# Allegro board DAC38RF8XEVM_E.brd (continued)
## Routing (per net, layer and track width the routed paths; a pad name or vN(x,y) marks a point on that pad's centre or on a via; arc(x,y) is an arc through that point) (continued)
VDD: length 143.1
  TOP w0.127: v1(68.5,30.2) 69.14,30.84 69.14,35.74 64.41,40.46 64.41,48.54 64.14,48.82 59.56,48.82 58.93,49.45 58.93,51.77 59.51,52.35 v1(59.51,52.4)
  TOP w0.305: v1(33.19,25.81) v1(33.99,26.61) ; v1(33.19,25.81) 33.15,25.81 ; v1(33.19,25.81) v1(33.19,25.01) ; v1(33.19,25.81) v1(33.99,25.81) ; v1(33.19,25.81) 33.55,25.45 33.63,25.45 ; v1(33.19,25.81) v1(33.19,26.61) ; v1(33.99,26.61) 34.37,26.23 ; v1(33.99,26.61) v1(33.19,27.41) ; v1(33.99,26.61) v1(33.99,25.81) ; v1(33.99,26.61) v1(32.39,25.81) ; v1(33.99,26.61) v1(33.19,26.61) ; v1(33.99,26.61) v1(33.19,25.01) ; v1(33.99,26.61) v1(33.99,27.41) ; v1(33.19,22.61) v1(33.19,23.41) v1(33.19,24.21) v1(33.19,25.01) ; 34.37,26.23 v1(33.99,25.81) ; 34.37,26.23 v1(34.79,25.81) ; v1(33.99,25.81) v1(33.19,27.41) ; v1(33.99,25.81) 33.63,25.45 ; v1(33.99,25.81) v1(34.79,25.81) ; v1(33.99,25.81) v1(33.19,26.61) ; v1(33.19,27.41) 33.63,27.41 ; v1(33.19,27.41) v1(33.19,26.61) ; v1(33.99,27.41) v1(33.19,26.61) ; v1(33.99,27.41) v1(33.19,25.01) ; v1(33.99,27.41) 33.63,27.41 ; v1(33.19,26.61) 32.77,25.43 ; v1(33.19,26.61) v1(32.39,25.81) ; v1(33.19,26.61) v1(34.79,25.81) ; 33.15,25.81 32.77,25.43 ; 33.15,25.81 v1(32.39,25.81) ; v1(33.19,25.01) 32.94,25.27 ; v1(33.19,25.01) 33.63,25.45 ; 33.63,27.41 32.94,25.27 ; 32.94,25.27 32.77,25.43 ; 32.77,25.43 v1(32.39,25.81) ; v1(32.39,25.81) v1(31.59,25.01)
  L3_PWR w0.102: 34.52,26.92 34.73,26.99 34.95,26.99 35.18,26.76 35.18,26.67 35.21,26.7 35.21,26.77 35.43,26.99 35.77,26.99 36.07,26.7 ; 31.45,24.64 31.45,24.61 31.21,24.37 31.21,24.05 31.4,23.86 ; 31.47,23.8 31.47,23.79 31.43,23.79 31.21,23.57 31.21,23.22 31.55,22.89
  L3_PWR w0.127: 58.75,26.77 58.43,27.09 57.96,27.09 57.64,26.77 57.48,26.77
  L4_SIG w0.305: 32.77,25.43 v1(32.39,25.81) ; 32.77,25.43 33.19,25.43 ; 32.77,25.43 32.77,25.81 ; v1(32.39,25.81) 32.79,26.21 ; v1(32.39,25.81) v1(31.59,25.01) ; v1(32.39,25.81) 32.77,25.81 ; v1(33.19,27.41) v1(33.99,27.41) ; v1(33.19,27.41) v1(33.99,26.61) ; v1(33.19,27.41) v1(33.19,26.61) ; v1(33.99,27.41) v1(33.19,26.61) ; v1(33.99,27.41) v1(33.99,26.61) ; v1(33.99,25.81) 34.26,25.81 ; v1(33.99,25.81) 33.6,25.43 ; v1(33.99,25.81) v1(33.19,26.61) ; v1(33.99,25.81) v1(33.99,26.61) ; v1(33.99,25.81) 33.6,25.81 ; 34.26,25.81 v1(34.79,25.81) 34.41,26.19 ; 34.26,25.81 34.26,26.03 34.41,26.19 ; 33.19,25.43 v1(33.19,25.81) ; 33.19,25.43 v1(33.19,25.01) ; v1(33.19,25.81) 32.77,25.81 ; v1(33.19,25.81) 33.19,26.21 ; v1(33.19,25.81) 33.6,25.81 ; v1(33.19,25.81) v1(33.99,26.61) ; v1(33.19,25.01) 33.6,25.43 ; v1(33.19,25.01) v1(33.19,24.21) v1(33.19,23.41) ; 33.6,25.43 33.6,25.81 ; v1(33.99,26.61) v1(33.19,26.61) ; v1(33.99,26.61) 34.41,26.19 ; 33.19,26.21 32.79,26.21 ; 33.19,26.21 v1(33.19,26.61) ; 32.79,26.21 v1(33.19,26.61)
  L6_PWR_SIG w0.305: v1(59.51,52.4) v1(59.51,53.52) 59.51,59.54 61.82,61.85 61.82,63.5 65.2,66.88 v1(65.94,66.88)
  BOTTOM w0.305: C117.1 33.18,25 v1(33.19,25.01) v1(33.99,25.81) ; C117.1 v1(33.19,24.21) v1(33.19,23.41) C118.1 ; C117.1 33.16,25.06 ; C117.1 33.63,27.41 ; v1(33.19,26.61) C127.1 34.8,25.81 v1(33.99,26.61) ; v1(33.19,26.61) v1(32.39,25.81) ; v1(33.19,26.61) v1(33.19,27.41) ; v1(33.19,26.61) v1(33.99,26.61) ; v1(33.19,26.61) v1(33.99,27.41) v1(33.99,26.61) ; v1(33.19,26.61) v1(33.99,25.81) ; v1(33.19,26.61) v1(33.19,25.81) ; v1(33.99,26.61) v1(32.39,25.81) ; v1(33.99,26.61) v1(33.19,25.81) ; v1(33.99,26.61) 32.69,25.53 ; v1(33.99,26.61) 33.99,26.23 ; v1(33.99,26.61) v1(33.19,27.41) ; C122.1 31.65,25.04 32.39,25.78 v1(32.39,25.81) ; 32.69,25.53 32.41,25.81 ; 32.69,25.53 32.96,25.26 ; 32.41,25.81 v1(33.19,25.81) ; 32.41,25.81 v1(32.39,25.81) ; 33.16,25.06 32.96,25.26 ; 33.16,25.06 33.16,25.4 ; 32.96,25.26 v1(33.19,27.41) ; v1(33.19,25.81) v1(33.99,25.81) ; v1(33.19,25.81) 33.16,25.79 33.16,25.4 ; v1(33.19,27.41) v1(33.99,25.81) ; v1(33.99,25.81) 33.99,26.23 ; v1(33.99,25.81) v1(34.79,25.81) ; 33.99,26.23 33.16,25.4
  BOTTOM w0.381: v1(33.99,27.41) v1(33.19,27.41)
  vias: v1(64.87,28.8) v1(65.63,28.8) v1(66.4,30.25) v1(66.4,28.81) v1(67.41,30.23) v1(67.46,28.8) v1(68.48,28.78) v2(33.28,21.31)
VDDE: length 20
  TOP w0.305: v1(31.59,26.61) v1(32.39,27.41) v1(31.59,28.21) 31.59,28.21 arc(31.99,28.59) 32.37,28.99 v1(32.39,29.01)
  L3_PWR w0.102: 32.81,28.37 32.79,28.37 32.66,28.5 ; 32.81,28.37 32.81,28.08 32.72,27.99 ; 32.81,28.37 32.81,28.39 33.05,28.63 ; 32.81,28.37 32.84,28.4 32.84,28.45 ; 32.74,28.68 32.84,28.45 ; 32.84,28.45 32.72,28.58 ; 32.84,28.45 32.84,28.6 ; 33.49,30.94 33.4,30.94 33.4,31.14 ; 33.49,30.94 33.49,30.85 33.57,30.85 ; 33.49,30.94 33.49,31.1 33.48,31.12 ; 33.6,31.27 33.57,31.23 33.57,30.85 ; 33.17,29.43 33.21,29.39 33.35,29.39 33.57,29.17 33.57,28.85 33.35,28.63 33.05,28.63 ; 33.17,29.43 33.35,29.43 33.57,29.66 33.57,29.97 33.35,30.19 33.21,30.19 33.17,30.23 ; 33.17,29.43 33.05,29.43 ; 32.57,27.84 32.72,27.99 ; 32.72,27.99 32.72,27.69 ; 33.17,30.23 33.35,30.23 33.57,30.45 33.57,30.85 ; 33.17,30.23 32.84,30.23 ; 32.84,28.6 32.92,28.6 ; 32.84,28.6 32.84,28.68 ; 33.05,28.63 33.03,28.63 32.96,28.7 ; 32,31.27 32,31.58 32.15,31.73
  L3_PWR w0.127: 32.56,31.83 32.54,31.81 32.23,31.81 32.15,31.73
  L4_SIG w0.305: v1(31.59,26.61) v1(32.39,27.41) v1(31.59,28.21) 31.59,28.21 arc(31.99,28.59) 32.37,28.99 v1(32.39,29.01)
  BOTTOM w0.254: 31.65,28.22 31.65,28.28 31.93,28.58 32.05,28.71 32.05,28.72 32.32,29.01 v1(32.39,29.01)
  BOTTOM w0.305: v1(32.39,27.41) 32.37,27.43 32.28,27.43 ; v1(34.52,35.13) 34.34,34.95 C119.1 33.68,34.95 v1(33.53,35.1) ; C125.1 32.38,29.01 v1(32.39,29.01) ; 32.28,27.43 C446.1 31.61,26.59 v1(31.59,26.61) ; 32.28,27.43 31.65,28.22 31.6,28.22 v1(31.59,28.21)
  vias: v1(48.03,37.03) v1(48.03,36.17) v1(49.25,37.06) v1(49.28,36.17)
VDDE_09:
  vias: v1(50.6,37.03) v1(50.6,36.25) v1(51.97,37.06) v1(51.97,36.22) v1(59.79,42.93) v1(59.82,42.06) v1(60.81,42.93) v1(60.83,42.06) v1(61.82,42.93) v1(61.85,42.06)
VDDOUT18:
  vias: v1(27.59,28.21) v1(27.59,27.41)
+1P8V:
  vias: v1(53.44,46.13) v1(53.44,45.19) v1(54.56,46.13) v1(54.56,45.19) v1(63.96,34.93) v1(63.96,33.81) v1(64.52,34.93) v1(64.52,33.81) v1(70.76,32.69) v1(70.76,32.13) v1(71.88,32.69) v1(71.88,32.13) v1(80.92,34.65) v1(80.92,34.09) v1(82.04,34.65) v1(82.04,34.09) v1(84.84,34.59) v1(84.84,34.04) v1(85.95,34.59) v1(85.95,34.04) v1(89,34.52) v1(89,33.96) v1(90.12,34.52) v1(90.12,33.96) v1(92.94,34.52) v1(92.94,33.96) v1(94.06,34.52) v1(94.06,33.96) v1(101.6,34.44) v1(101.6,33.88) v1(102.72,34.44) v1(102.72,33.88)
ALARM: length 57.1
  TOP w0.102: v1(30.79,29.81) 30.79,29.82 30.41,30.19 30.41,30.77 30.63,30.99 30.92,30.99 31.18,31.25 31.18,31.58 31.03,31.73
  TOP w0.127: 26.75,39.85 30.71,35.89 30.71,32.05 31.03,31.73
  TOP w0.152: v1(26.75,40.84) 26.75,39.85
  L3_PWR w0.127: TP9.1 33.55,60.2 29.36,56.01 29.08,56.01 28.46,55.38 28.46,55.01 27.93,54.48 21.84,54.48 20.15,52.79 20.15,45.38 20.79,44.74 20.8,44.74 21.07,44.47 21.07,44.47 23.04,42.49 26.16,42.49 26.75,41.91 v1(26.75,40.84)
AMUX0: length 64.4
  L4_SIG w0.102: v1(34.79,27.41) 35.17,27.03 35.86,27.03 36.56,26.33 36.56,23.3 36.79,23.08
  L4_SIG w0.127: v1(10.56,50.36) 8.5,50.36 7.59,49.45 7.59,45.57 8.76,44.4 11.68,44.4 13.77,42.32 13.77,41.43 14.41,40.78 15.55,40.78 16.32,40.01 16.32,39.64 16.14,39.47 16.14,39.03 17.27,37.9 18.11,37.9 20.91,35.09 21.01,35.09 21.27,34.83 21.27,31.66 22.53,30.4 22.53,24.87 22.96,24.44 22.96,23.65 24.64,21.97 24.64,20.68 25.14,20.18 25.44,20.18 25.47,20.15 25.84,20.15 25.87,20.18 26.25,20.18 27.37,21.3 30.9,21.3 33.06,19.14 34.76,19.14 36.97,21.35 36.97,22.9 36.79,23.08
AMUX1: length 54.3
  L4_SIG w0.102: v1(34.79,26.61) 35.21,26.19 35.75,26.19 36.12,25.82 36.12,22.45 35.9,22.23 35.88,22.23 35.86,22.21
  L4_SIG w0.127: v1(8.56,49.43) 7.98,48.84 7.98,45.87 8.94,44.91 11.85,44.91 15.41,41.36 15.41,41.34 15.67,41.08 15.68,41.08 16.62,40.14 16.62,39.91 22.73,33.8 22.73,31.67 23.52,30.89 23.52,29.72 23.43,29.63 23.43,26.56 23.77,26.21 23.77,24.9 24.03,24.64 24.03,23.39 25.09,22.33 25.5,22.33 26.1,21.73 26.1,21.55 26.3,21.35 26.58,21.35 26.84,21.6 31.38,21.6 32.72,20.26 33.48,20.26 35.4,22.19 35.84,22.19 35.86,22.21
ATEST: length 36.2
  L4_SIG w0.102: 27.28,22.99 28.55,22.99 28.86,22.68 29.8,22.68 30.41,23.29 30.41,23.83 v1(30.79,24.21)
  L4_SIG w0.127: 27.28,22.99 26.77,23.51 26.77,35.94 21.77,40.94 20.65,40.94 15.38,46.22 v1(12.57,46.22)
CAR_SYSREF_M: length 8.5
  BOTTOM w0.229: R23.1 120.98,40.06 R24.1 120.02,40.26 119.35,40.26 116.2,43.4 116.2,44.75 116.15,44.81 U2.4
CAR_SYSREF_P: length 8.5
  BOTTOM w0.229: U2.3 116.65,44.81 116.59,44.75 116.59,43.56 118.41,41.74 118.69,41.74 118.79,41.84 119.07,41.84 119.27,41.64 119.27,41.35 119.18,41.26 119.18,40.97 119.51,40.64 119.99,40.64 R25.1 120.98,40.87 R22.1
CAR_SYSREFM: length 28
  BOTTOM w0.165: J20.G10 146.05,47.88 145.8,48.13 141.96,48.13 141.88,48.04 141.86,48.04
  BOTTOM w0.229: R23.2 122.16,40.08 122.35,40.27 133.77,40.27 141.55,48.04 141.86,48.04
CAR_SYSREFP: length 28
  BOTTOM w0.165: 141.86,48.43 141.88,48.43 141.92,48.38 145.79,48.38 146.05,48.64 J20.G9
  BOTTOM w0.229: R22.2 122.16,40.84 122.35,40.65 133.62,40.65 141.39,48.43 141.86,48.43
CLK-IN: length 3.4
  BOTTOM w0.483: T3.6 100.96,58.24 R34.1 97.6,58.24 R32.2
CLK_LAO_0M: length 27.1
  BOTTOM w0.165: 141.86,51.92 141.9,51.92 141.93,51.95 145.76,51.95 146.05,51.66 J20.G7
  BOTTOM w0.229: R57.2 123.29,47.09 124.61,47.09 125.65,46.05 127.48,46.05 128.45,47.02 129.97,47.02 130.91,46.08 132.66,46.08 133.45,46.86 135.59,46.86 140.65,51.92 141.86,51.92
CLK_LAO_0P: length 27.1
  BOTTOM w0.165: 141.86,52.3 141.88,52.3 141.98,52.2 145.78,52.2 146.05,52.48 J20.G6
  BOTTOM w0.229: R55.2 123.22,47.47 124.77,47.47 125.81,46.43 127.32,46.43 128.29,47.4 130.13,47.4 131.07,46.46 132.51,46.46 133.29,47.24 135.43,47.24 140.49,52.3 141.86,52.3
CLKIN1_N: length 6.6
  BOTTOM w0.229: U2.35 111.14,55.72 111.08,55.78 111.08,58.42 C37.2 109.54,59.89 v1(108.71,59.89)
CLKIN1_P: length 6
  BOTTOM w0.229: U2.34 110.64,55.72 110.7,55.78 110.7,58.21 109.45,59.46 109.05,59.46 C35.2
  vias: v1(108.71,59.13)
CLKINN: length 4.2
  BOTTOM w0.483: T3.3 105.49,60.78 R35.2 106.38,59.89 C36.1
CLKINP: length 4.2
  BOTTOM w0.483: C35.1 107.24,59.13 R29.1 106.4,59.11 R35.1 105.53,58.24 T3.1
CLKLA_0M: length 4
  BOTTOM w0.229: R57.1 122.33,46.84 R58.1 121.15,46.84 120.91,47.07 119.41,47.07 119.35,47.01 U2.63
CLKLA_0P: length 4
  BOTTOM w0.229: R55.1 122.33,47.65 R56.1 121.15,47.65 120.95,47.45 119.41,47.45 119.35,47.51 U2.62
CLKN: length 98
  BOTTOM w0.229: v2(30.55,19.11) 29.95,19.11 29.72,18.89 29.72,18.56 30.07,18.21 30.97,18.21 arc(31.21,18.31) 31.31,18.55 arc(31.65,18.9) 31.99,18.55 arc(32.1,18.31) 32.34,18.21 34.01,18.21 38.75,22.96 103.66,22.96 104.5,23.8 104.5,24.09 104.44,24.15 104.44,24.43 104.64,24.63 104.93,24.63 104.99,24.57 105.27,24.57 105.64,24.94 105.64,38.51 106.54,39.41 106.54,40.96 R36.2
CLKP: length 98
  BOTTOM w0.229: R31.2 106.92,40.96 106.92,39.25 106.02,38.35 106.02,24.78 103.82,22.58 38.91,22.58 34.16,17.83 29.91,17.83 29.34,18.4 29.34,18.88 29.11,19.11 v2(28.52,19.11)
CP1: length 35.2
  L6_PWR_SIG w0.305: v1(107.37,54.03) 111.23,54.03 113.26,56.06 113.28,56.06 113.31,56.09 113.34,56.09 113.44,56.18 114.27,56.18 116.28,58.19 124.54,58.19 129.59,63.25 v1(136.8,63.25)
  BOTTOM w0.305: v1(107.37,54.03) 107.37,54.02 U2.32
  vias: v1(137.57,63.25)
CP2: length 2.2
  TOP w0.305: v1(116.65,55.53) 116.65,54.88 C34.1 C33.1
  BOTTOM w0.305: U2.46 v1(116.65,55.53)
DAC_RESET: length 149.6
  L4_SIG w0.102: v1(29.99,29.81) 29.61,30.19 29.61,31.73
  L4_SIG w0.127: 29.61,31.73 29.61,34.09 26.5,37.2 25.95,37.2 24.66,38.49 24.66,38.96 14.45,49.17 14.45,54.71 17.2,57.45 19.35,57.45 v1(20.42,58.52) 24.05,62.15 25.1,62.15 26.26,63.32 29.13,63.32 29.42,63.61 29.42,64.02 29.71,64.31 33.03,64.31 33.11,64.22 35.31,64.22 35.4,64.31 35.4,64.31 35.51,64.41 36.84,64.41 37,64.25 39.23,64.25 39.93,64.95 43.18,64.95 43.61,64.52 50.42,64.52 51.33,63.6 61.19,63.6 62.48,64.9 70.23,64.9 72.75,62.38 81.67,62.38 81.88,62.17 82.25,62.17 82.58,62.5 83.04,62.5 83.27,62.26 86.52,62.26 86.78,62.52 91.2,62.52 93.14,64.47 94.82,64.47 95.55,63.73 97.95,63.73 100.37,66.14 117.2,66.14 118.64,64.7 v1(118.64,64.62) 121.14,64.62 SW1.2
  BOTTOM w0.127: R11.2 v1(118.64,64.62)
DAC_SCLK: length 43.1
  L4_SIG w0.127: v1(52.81,55.3) 52.81,55.19 52.3,54.69 49.98,54.69 48.89,55.78 46.28,55.78 43.92,53.42 43.14,53.42 42.67,53.89 41.97,53.89 41.86,53.77 38.93,53.77 38.92,53.78 38.55,53.78 38.54,53.77 34.79,53.77 34.78,53.76 33.82,53.76 33.41,53.35 29.29,53.35 29.09,53.56 28.72,53.56 28.59,53.43 27.06,53.43 26.34,54.15 22.61,54.15 22.36,53.9 21.26,53.9 20.61,53.25 v1(20.61,48.43)
  BOTTOM w0.127: U29.6 53.26,57.41 53.42,57.25 53.42,55.75 52.96,55.3 v1(52.81,55.3)
DAC_SDENB: length 40.7
  L4_SIG w0.127: v2(52.68,55.91) 52.58,56.01 49.83,56.01 48.92,56.92 46.1,56.92 44.27,55.09 42.19,55.09 41.95,54.85 41.36,54.85 41.33,54.83 40.96,54.83 40.94,54.85 40.21,54.85 40.01,54.65 30.31,54.65 30.18,54.78 29.81,54.78 29.76,54.72 20.56,54.72 19.63,53.8 19.63,50.75 18.6,49.71 v1(18.6,48.43)
DAC_SDIO: length 52.5
  L4_SIG w0.127: v2(52.68,56.91) 53.19,57.42 53.19,61.8 52.35,62.64 48.58,62.64 48.11,63.11 45.22,63.11 44.55,62.43 41.53,62.43 41.33,62.64 40.64,62.64 40.5,62.5 39.26,62.5 39.18,62.57 31.02,62.57 30.38,63.21 29.68,63.21 29.31,62.84 28.54,62.84 27.62,61.93 27.62,61.82 27.27,61.47 24.18,61.47 20.65,57.94 20.65,56.37 19.95,55.66 19.67,55.66 19.23,55.22 19.23,51.06 v1(16.59,48.43)
DAC_SDO: length 40.1
  L4_SIG w0.127: v2(52.68,56.41) 53.31,55.77 53.31,55.04 52.48,54.2 49.56,54.2 48.98,54.78 46.42,54.78 44.58,52.93 40.31,52.93 39.71,52.34 27.29,52.34 26.06,53.57 23.37,53.57 22.59,52.79 v1(22.59,47.51)
DACCLK_IN: length 3.3
  TOP w0.483: J1.1 5.33,8.1 R215.2
DACCLK_N: length 3.1
  TOP w0.229: C334.2 29.74,19.91 29.74,22.37 U1.A9
DACCLK_P: length 3.1
  TOP w0.229: U1.A10 29.36,22.44 29.36,19.96 C333.2
DACCLK_SE: length 4.1
  TOP w0.483: C370.2 26.75,14.13 R2.1 C25.1 R1.2
DACCLKSE: length 4.4
  TOP w0.483: R1.1 26.75,18.59 27.08,18.92 R3.1 27.08,21.38 arc(27.13,21.81) 27.29,22.21 arc(27.43,22.42) U1.A12
DCLKOUT4P: length 1.5
  BOTTOM w0.229: v1(108.03,49.53) 108.51,50.02 U2.24
DIV_IN: length 96.6
  TOP w0.483: R214.2 9.53,12.21 v1(9.52,12.22)
  BOTTOM w0.406: v1(9.52,12.22) 10.23,12.93 arc(10.8,13.77) 11,14.77 11,38.1 arc(11.22,39.21) 11.85,40.15 11.85,40.15 arc(12.42,40.53) 13.09,40.67 22,40.67 arc(22.86,40.49) 23.6,40 24.5,39.1 arc(25.22,38.62) 26.06,38.46 71.27,38.46 arc(72.97,38.79) 74.41,39.76 R243.1
  BOTTOM w0.483: R243.1 75.94,41.27 C378.1
DM: length 5.6
  BOTTOM w0.229: J16.2 7.25,56.43 7.46,56.64 8.15,56.64 9.87,54.91 10.57,54.91 R65.1
DP: length 5.6
  BOTTOM w0.229: J16.3 7.32,57.23 7.53,57.02 8.31,57.02 10.03,55.3 10.54,55.3 R66.1
DP0_C2M_N_A: length 131.8
  TOP w0.229: v2(151.13,56.52) 150.69,56.96 150.36,56.96 148.93,55.53 148.93,55.51 148.82,55.39 148.82,45.64 146.77,43.59 141.07,43.59 135.53,38.05 133.12,38.05 117.32,22.25 59.41,22.25 46.3,35.36 45.26,35.36 45.14,35.23 C24.1
DP0_C2M_P_A: length 131.8
  TOP w0.229: C23.1 45.14,35.92 45.31,35.74 46.46,35.74 59.57,22.63 117.17,22.63 132.96,38.43 135.38,38.43 140.91,43.97 146.61,43.97 148.44,45.8 148.44,55.55 148.55,55.66 148.55,55.69 150.2,57.34 150.69,57.34 v2(151.13,57.79)
DP1_C2M_N_A: length 124.4
  TOP w0.229: v2(153.67,31.12) 154.12,31.57 154.59,31.57 155.04,32.02 155.04,33.51 154.31,34.24 145.26,34.24 131.67,20.65 58.78,20.65 46.2,33.22 45.31,33.22 C21.1
DP1_C2M_P_A: length 124.3
  TOP w0.229: C22.1 45.34,32.84 46.04,32.84 58.62,20.27 131.83,20.27 144.15,32.6 arc(144.32,32.67) 144.48,32.6 arc(144.65,32.53) 144.81,32.6 144.97,32.75 arc(145.04,32.92) 144.97,33.08 arc(144.9,33.25) 144.97,33.41 145.41,33.86 149.62,33.86 arc(149.83,33.77) 149.92,33.55 arc(150.01,33.34) 150.23,33.25 150.31,33.25 arc(150.52,33.34) 150.61,33.55 arc(150.7,33.77) 150.91,33.86 154.15,33.86 154.66,33.35 154.66,32.17 154.43,31.95 154.11,31.95 v2(153.67,32.38)
DP2_C2M_N_A: length 117.4
  TOP w0.229: v2(153.67,26.03) 153.31,26.39 142.39,26.39 141.16,25.16 141.16,24.98 140.49,24.31 140.31,24.31 133.93,17.93 58.19,17.93 46.02,30.1 45.26,30.1 C18.1
DP2_C2M_P_A: length 117.4
  TOP w0.229: C19.1 45.39,30.48 46.18,30.48 58.35,18.31 133.78,18.31 142.23,26.77 153.16,26.77 153.67,27.28 v2(153.67,27.3)
DP3_C2M_N_A: length 121.6
  TOP w0.229: v2(153.67,20.95) 153.67,21.11 153.92,21.36 154.41,21.36 154.99,21.94 154.99,23.27 154.36,23.9 142.39,23.9 134.47,15.98 57.94,15.98 46.1,27.81 45.39,27.81 C17.1
DP3_C2M_P_A: length 121.6
  TOP w0.229: v2(153.67,22.23) 153.67,22 153.92,21.74 154.25,21.74 154.61,22.1 154.61,23.11 154.2,23.52 151.03,23.52 150.7,23.19 150.22,23.19 149.89,23.52 148.44,23.52 148.09,23.17 147.77,23.17 147.42,23.52 145.85,23.52 145.54,23.22 145.08,23.22 144.78,23.52 142.55,23.52 141.23,22.2 arc(141.17,22.07) 141.23,21.93 arc(141.28,21.8) 141.23,21.67 141.01,21.45 arc(140.88,21.39) 140.74,21.45 arc(140.61,21.5) 140.48,21.45 134.63,15.6 57.78,15.6 45.94,27.43 45.26,27.43 C16.1
DP4_C2M_N_A: length 120.4
  TOP w0.229: v2(153.67,15.88) 154.11,16.32 154.6,16.32 155.05,16.77 155.05,17.7 154.48,18.26 153.23,18.26 152.62,17.65 143.76,17.65 137.43,11.33 57.07,11.33 45.87,22.53 45.34,22.53 C13.1
DP4_C2M_P_A: length 120.4
  TOP w0.229: v2(153.67,17.14) 154.11,16.7 154.44,16.7 154.67,16.93 154.67,17.54 154.32,17.88 153.39,17.88 152.78,17.27 152.42,17.27 arc(152.18,17.17) 152.08,16.93 152.08,16.88 arc(151.73,16.54) 151.39,16.88 151.39,16.93 arc(151.29,17.17) 151.05,17.27 143.92,17.27 141.45,14.81 141.45,14.15 141.2,13.89 140.54,13.89 137.59,10.95 56.92,10.95 45.71,22.15 45.31,22.15 C14.1
DP5_C2M_N_A: length 119.3
  TOP w0.229: C10.1 45.34,17.2 45.8,17.2 56.29,6.71 141.14,6.71 141.43,6.99 arc(141.53,7.24) 141.43,7.48 141.41,7.5 arc(141.41,7.99) 141.9,7.99 141.92,7.97 arc(142.16,7.86) 142.4,7.97 143.23,8.79 153.9,8.79 154.66,9.55 154.66,9.72 arc(154.58,9.93) 154.37,10.01 154.37,10.01 arc(154.18,10.21) 154.37,10.4 154.47,10.4 arc(154.6,10.45) 154.66,10.59 154.66,11.01 154.43,11.23 154.11,11.23 v2(153.67,10.79)
DP5_C2M_P_A: length 119.1
  TOP w0.229: v2(153.67,12.06) 154.12,11.61 154.59,11.61 155.04,11.16 155.04,9.39 154.06,8.41 143.38,8.41 141.3,6.32 56.13,6.32 45.64,16.81 45.31,16.81 C11.1
DP6_C2M_N_A: length 114.1
  TOP w0.229: C8.1 45.31,19.48 45.74,19.48 56.51,8.71 139.22,8.71 144.27,13.77 151.97,13.77 v2(152.4,13.33)
DP6_C2M_P_A: length 114.1
  TOP w0.229: v2(152.4,14.61) 151.94,14.15 144.11,14.15 139.06,9.09 56.67,9.09 45.9,19.86 45.34,19.86 C9.1
DP7_C2M_N_A: length 115.9
  TOP w0.229: v2(152.4,18.41) 151.92,18.9 150.46,18.9 148.99,20.37 143.21,20.37 136.07,13.23 57.35,13.23 45.79,24.79 45.29,24.79 C5.1
DP7_C2M_P_A: length 115.9
  TOP w0.229: C6.1 45.36,25.17 45.95,25.17 57.51,13.61 135.91,13.61 143.05,20.75 149.15,20.75 150.62,19.28 151.99,19.28 v2(152.4,19.69)
EEDATA: length 4.6
  TOP w0.127: R74.1 36.6,50.8 v1(36.56,50.84) 36.56,51.06 36.91,51.41 36.91,52.62 U5.3
  BOTTOM w0.127: U4.61 v1(36.56,50.84)
EXTIO: length 2.3
  BOTTOM w0.102: 27.28,23.79 28.54,23.79 28.96,24.21 v1(29.19,24.21)
  BOTTOM w0.127: 27.28,23.79 27.07,23.79 C28.1
FMC_DAC_SCLK: length 149.6
  L4_SIG w0.127: v1(25.88,43.71) 25.88,43.61 29.11,40.39 29.69,40.39 30.59,39.48 30.59,39.06 30.85,38.8 31.07,38.8 31.92,37.95 31.92,37.71 32.93,36.69 33.39,36.69 34.51,35.57 34.99,35.57 35.64,34.92 35.64,34.47 37.88,32.22 37.88,32 38.58,31.3 38.58,30.43 41.48,27.53 54.79,27.53 57.05,25.27 118.24,25.27 118.4,25.11 122.24,25.11 127.48,30.35 127.48,30.78 127.97,31.27 128.32,31.27 132.47,35.42 133.49,35.42 134.53,36.46 137.47,36.46 137.89,36.04 141.48,36.04 141.97,35.55 144.83,35.55 145.41,36.13 145.41,36.4 145.81,36.8 146.09,36.8 146.55,37.26 146.55,37.52 147.26,38.24 147.53,38.24 147.82,38.53 147.82,38.79 148.53,39.51 148.8,39.51 149.36,40.08 149.36,40.21 149.78,40.63 151.18,40.63 151.71,41.16 151.71,41.96 v3(151.13,42.55)
  BOTTOM w0.127: R289.2 22.1,44.73 22.91,44.73 23.93,43.71 v1(25.88,43.71)
FMC_DAC_SDENB: length 146.7
  L4_SIG w0.127: v3(149.86,41.27) 149.29,40.7 148,40.7 147.82,40.52 147.82,39.8 147.53,39.51 147.11,39.51 146.55,38.94 146.55,38.53 146.13,38.12 145.83,38.12 145.43,37.71 145.43,37.41 144.99,36.97 136.66,36.97 136.55,36.86 132.23,36.86 125.17,29.79 104.65,29.79 104.01,30.43 100.96,30.43 99.78,31.61 94.73,31.61 94.53,31.41 92.75,31.41 92.73,31.43 83.93,31.43 83.76,31.61 69.74,31.61 69.19,31.06 65.71,31.06 64.33,29.68 61.05,29.68 60.1,30.63 57.15,30.63 56.29,29.77 55.52,29.77 54.89,30.4 52.53,30.4 52.12,30 49.3,30 48.95,30.35 43,30.35 42.55,29.9 41,29.9 38.99,31.9 38.99,32.15 37.09,34.05 36.7,34.05 36.2,34.55 36.2,35.5 34.89,36.8 33.86,36.8 33.16,37.5 33.16,37.85 32.9,38.11 32.37,38.11 31.48,39 31.48,39.43 31.22,39.69 30.98,39.69 28.18,42.48 28.18,42.58 27.92,42.84 27.83,42.84 26.52,44.15 v1(26.52,44.2)
  BOTTOM w0.127: v1(26.52,44.2) 24.14,44.21 23.19,45.16 19.84,45.16 R290.2
FMC_DAC_SDIO: length 149.6
  L4_SIG w0.127: v3(151.13,41.27) 150.55,41.86 146.97,41.86 146.61,41.5 146.61,39.86 146.26,39.51 146.06,39.51 145.28,38.72 145.28,38.53 144.92,38.18 141.28,38.18 141,37.9 132.61,37.9 124.9,30.19 106.46,30.19 103.43,33.22 66.31,33.22 64.76,31.67 61.54,31.67 61.49,31.72 54.48,31.72 54.15,31.39 49.07,31.39 48.54,30.86 41.17,30.86 40.08,31.95 40.08,32.23 38.94,33.38 38.56,33.38 37.49,34.44 37.49,34.72 35,37.21 33.88,37.21 33.46,37.63 33.46,37.98 33.03,38.42 32.68,38.42 31.79,39.31 31.79,39.71 31.39,40.11 31.08,40.11 27.15,44.04 v1(27.15,44.7)
  BOTTOM w0.127: R291.2 18.08,46 22.99,46 24.27,44.71 27.14,44.71 v1(27.15,44.7)
FMC_DAC_SDO: length 152.3
  L4_SIG w0.127: v1(25.27,43.15) 25.83,43.15 29.01,39.98 29.56,39.98 30.09,39.45 30.09,39.15 30.29,38.95 30.29,38.93 30.73,38.49 30.75,38.49 31.15,38.09 31.35,38.09 31.61,37.83 31.61,37.43 32.65,36.38 33.14,36.38 33.97,35.55 33.97,34.89 34.62,34.24 35,34.24 38.25,30.99 38.25,30.15 39.41,28.99 39.41,28.99 39.61,28.79 39.61,28.79 41.35,27.05 54.24,27.05 56.68,24.61 122.45,24.61 127.08,29.24 128.4,29.24 128.8,29.64 128.8,30.96 132.77,34.93 133.76,34.93 134.31,35.47 138.01,35.47 139.06,34.43 143.79,34.43 144.04,34.68 145.01,34.68 145.8,35.47 146.12,35.47 146.88,36.23 146.88,36.38 147.14,36.64 147.28,36.64 148.09,37.45 148.09,37.67 148.38,37.96 148.6,37.96 150.06,39.42 151.27,39.42 151.9,40.05 151.9,40.21 152.19,40.5 152.36,40.5 153.11,41.25 153.11,42.57 152.53,43.15 150.47,43.15 v3(149.86,42.55)
  BOTTOM w0.127: R288.2 v1(25.27,43.15)
FMC_LMK_CS: length 102.2
  L4_SIG w0.127: v1(56.11,59.18) 57.96,59.18 63.02,54.13 64.87,54.13 65.94,55.19 71.04,55.19 72.58,53.66 78.09,53.66 78.2,53.77 78.67,53.77 78.78,53.66 79.15,53.66 79.52,54.03 81.81,54.03 82.3,54.51 89.41,54.51 89.69,54.23 90.55,54.23 90.83,54.51 92.74,54.51 94.83,56.6 101.26,56.6 103.19,54.67 105.88,54.67 108.41,52.15 109.93,52.15 110.31,51.77 117.37,51.77 119,50.14 120.27,50.14 120.62,50.5 133.2,50.5 134.67,49.02 134.67,48.23 138.02,44.88 138.48,44.88 139.24,44.12 139.24,43.31 141.77,40.78 142.17,40.78 142.74,40.21 142.74,39.84 143.28,39.29 144.22,39.29 v3(144.78,38.73)
FMC_LMK_SCK: length 102.3
  L4_SIG w0.127: v3(146.05,41.27) 145.36,41.96 145.36,42.75 144.93,43.18 144.22,43.18 142.74,44.67 142.74,45.29 142.45,45.58 141.77,45.58 135.92,51.43 135.92,52.91 135.51,53.31 128.96,53.31 127.9,54.37 127.48,54.37 127.22,54.63 127.22,55.05 124.99,57.28 111.28,57.28 110.77,56.77 109.4,56.77 108.89,57.28 106.93,57.28 105.36,58.85 94.59,58.85 93.7,57.96 81.65,57.96 79.6,60.02 70.43,60.02 70.15,60.3 67.72,60.3 66.73,61.29 63.17,61.29 62.71,60.83 59,60.83 57.23,62.61 v1(56.11,62.61)
FMC_LMK_SDIO: length 103.9
  L4_SIG w0.127: v1(56.11,61.47) 57.3,61.47 61.11,57.66 63.3,57.66 63.6,57.96 68.2,57.96 68.29,58.05 70.12,58.05 70.4,57.77 72.33,57.77 74.24,59.69 78.91,59.69 82.8,55.8 84.83,55.8 85.13,55.5 86.26,55.5 86.56,55.8 92.41,55.8 94.97,58.37 104.85,58.37 107.48,55.74 107.48,55.69 109.11,54.05 114.96,54.05 114.97,54.06 118.45,54.06 121.12,51.4 134.22,51.4 136.99,48.62 137.89,48.62 139.55,46.96 139.55,46.26 142.8,43.01 142.8,42.56 143.3,42.05 143.44,42.05 144.12,41.37 144.12,41.23 144.69,40.67 145.39,40.67 v3(146.05,40.01)
FMC_LMK_SDO: length 102.6
  L4_SIG w0.127: v1(56.11,60.33) 57.63,60.33 63.3,54.66 64.77,54.66 65.89,55.78 71.45,55.78 72.57,54.66 81.48,54.66 82.26,55.44 84.77,55.44 85.06,55.14 86.72,55.14 86.98,55.41 89.2,55.41 89.91,54.7 90.28,54.7 90.65,55.07 92.48,55.07 95.38,57.96 104.7,57.96 108.24,54.42 108.27,54.42 109.84,52.84 118.86,52.84 120.75,50.95 133.34,50.95 136.58,47.71 136.61,47.71 138.84,45.49 139.24,45.49 140.88,43.85 140.88,42.49 141.32,42.05 142.33,42.05 142.82,41.55 142.82,41.26 143.3,40.78 144.01,40.78 v3(144.78,40.01)
FPGA_CLK1_N: length 20.4
  BOTTOM w0.165: J20.K5 141.86,54.36
  BOTTOM w0.229: C43.2 124.09,50.47 124.28,50.66 137.18,50.66 140.95,54.43 141.78,54.43 141.86,54.36
FPGA_CLK1_P: length 20.4
  BOTTOM w0.165: J20.K4 141.86,54.86
  BOTTOM w0.229: C42.2 124.09,51.23 124.28,51.04 137.02,51.04 140.79,54.81 141.81,54.81 141.86,54.86
FPGA_CLK1N: length 5.7
  BOTTOM w0.229: U2.52 119.35,52.52 119.41,52.58 119.73,52.58 120.52,51.79 120.52,51.31 121.16,50.67 121.92,50.67 R46.1 122.91,50.44 C43.1
FPGA_CLK1P: length 5.7
  BOTTOM w0.229: C42.1 122.91,51.26 R45.1 121.95,51.05 121.32,51.05 120.9,51.47 120.9,51.95 119.89,52.96 119.41,52.96 119.35,53.02 U2.51
FPGA_CLK2_N: length 22.5
  BOTTOM w0.165: 141.86,56.96 141.9,56.96 141.96,57.02 143.23,57.02 143.51,56.74 J20.J3
  BOTTOM w0.229: C48.2 123.3,53.37 123.49,53.56 137.83,53.56 141.24,56.96 141.86,56.96
FPGA_CLK2_P: length 22.5
  BOTTOM w0.165: J20.J2 143.51,57.53 143.26,57.28 141.96,57.28 141.9,57.34 141.86,57.34
  BOTTOM w0.229: 141.86,57.34 141.08,57.34 137.68,53.94 123.49,53.94 123.3,54.13 C47.2
FPGA_CLK2N: length 3.8
  BOTTOM w0.229: C48.1 122.12,53.34 R50.1 121.12,53.58 119.41,53.58 119.35,53.52 U2.50
FPGA_CLK2P: length 3.8
  BOTTOM w0.229: U2.49 119.35,54.02 119.41,53.96 121.17,53.96 R51.1 122.12,54.15 C47.1
FTDI_TCK: length 57.1
  L3_PWR w0.127: v1(51.8,59.78) 51.27,59.25 50.11,59.25 49.77,58.91 49.77,57.77 49.12,57.11 38.34,57.11 37.39,56.16 35.24,56.16 34.72,55.64 34.43,55.64 31.64,52.84 31.64,52.6 30.93,51.89 v1(26.06,51.89)
  L4_SIG w0.102: v1(33.99,29.81) 34,29.81 34.41,30.22 34.41,31.73
  L4_SIG w0.127: 34.41,31.73 31.88,34.26 31.88,34.82 31.21,35.5 31.2,35.5 30.94,35.76 30.94,35.76 26.61,40.09 26.44,40.09 26,40.53 26,40.7 24.26,42.44 24.26,50.09 v1(26.06,51.89)
FTDI_TDI: length 69.5
  L3_PWR w0.127: v1(23.65,53.09) 25.35,51.38 31.19,51.38 33.57,53.76 35.88,53.76 38.09,55.97 50.12,55.97 50.12,55.98 50.49,55.98 50.5,55.97 51.9,55.97 52.26,56.33 52.26,58.49 v2(52.68,58.91)
  L4_SIG w0.102: 36.09,31.73 36.09,29.69 35.83,29.43 34.56,29.43 34.39,29.26 34.39,28.62 v1(33.99,28.21)
  L4_SIG w0.127: 36.09,31.73 36.09,31.9 32.13,35.87 32.13,36.38 31.32,37.2 30.98,37.2 30.72,37.46 30.72,37.79 29.68,38.82 29.46,38.82 29.2,39.08 29.2,39.19 28.82,39.57 28.82,39.58 28.38,40.02 28.36,40.02 26.63,41.75 26.63,41.92 26.1,42.44 25.17,42.44 24.66,42.95 24.66,49.63 26.59,51.56 26.59,52.25 25.76,53.09 v1(23.65,53.09)
FTDI_TDO: length 70.4
  L3_PWR w0.127: v2(52.68,58.41) 52.84,58.41 53.64,57.61 53.64,54.92 52.37,53.64 42.79,53.64 42.55,53.89 37.91,53.89 36.09,52.07 33.83,52.07 31.22,49.45 25.45,49.45 22.38,52.53 v1(22.38,53.29)
  L4_SIG w0.102: 32.83,31.73 33.61,30.96 33.61,29.38 33.98,29.01 v1(33.99,29.01)
  L4_SIG w0.127: 32.83,31.73 32.64,31.93 31.22,31.93 30.81,32.33 30.81,34.85 28.44,37.22 28.01,37.22 27.75,37.48 27.75,38.34 25.12,40.97 24.69,40.97 22.15,43.51 22.15,47.33 22.15,47.33 22.15,47.69 22.15,47.7 22.15,53.06 v1(22.38,53.29)
FTDI_TMS: length 69.1
  L3_PWR w0.127: v1(21.39,53.29) 21.92,53.82 22.63,53.82 23.04,53.42 23.04,52.73 25.65,50.11 30.84,50.11 33.3,52.58 35.59,52.58 37.83,54.83 40.19,54.83 40.21,54.85 40.94,54.85 40.96,54.83 41.69,54.83 41.94,55.07 43.48,55.07 43.92,54.64 52.77,54.64 53.25,55.11 53.25,57.32 52.68,57.89 v2(52.68,57.91)
  L4_SIG w0.102: v1(33.19,29.81) 33.19,30.06 32.83,30.41 32.83,30.43 32.81,30.45 32.81,30.82 32.61,31.02 32.15,31.02 31.7,31.47 31.01,31.47 30.75,31.73
  L4_SIG w0.127: v1(21.39,53.29) 21.39,45.11 21.79,44.7 21.79,43.23 25.57,39.46 25.57,39.06 25.83,38.8 26.53,38.8 27.28,38.05 27.28,37.52 27.88,36.92 28.11,36.92 30.4,34.62 30.4,32.08 30.75,31.73
FTDI_TRSTB: length 36.7
  TOP w0.127: R177.1 21.39,58.34 21.39,57.02 21.67,56.74 21.67,54.97 v1(20.98,54.28)
  L4_SIG w0.102: 30.15,31.73 30.77,31.12 31.67,31.12 32.01,30.78 32.01,30.45 32.23,30.23 32.55,30.23 32.81,29.97 32.81,29.39 v1(33.19,29.01)
  L4_SIG w0.127: 30.15,31.73 30.02,31.86 30.02,34.24 26.87,37.39 26.87,37.69 26.07,38.49 25.64,38.49 25.26,38.87 25.26,39.15 21.03,43.38 21.03,44.08 21.05,44.1 21.05,44.47 21.03,44.49 21.03,44.55 20.16,45.42 20.16,53.46 v1(20.98,54.28)
GPIO0: length 63.6
  L3_PWR w0.127: v1(99.39,38.76) 99.39,36.86 100.84,35.41 100.84,32.51 100.85,32.49 100.85,27.91 100.84,27.9 100.84,26.9 100.55,26.61 100.55,23.84 101.35,23.04 104.88,23.04 104.99,23.15 131.33,23.15 135,26.82 138.07,26.82 138.68,27.43 139.97,27.43 140.68,26.72 v1(140.74,26.72)
  BOTTOM w0.127: 141.86,26.72 v1(140.74,26.72)
  BOTTOM w0.165: J20.H28 144.28,25.27 144.28,26.13 143.69,26.72 141.86,26.72
GPIO1: length 60.9
  L3_PWR w0.127: v1(99.42,36.17) 99.95,35.64 99.95,26.9 100.18,26.67 100.18,23.37 101.14,22.4 105.26,22.4 105.64,22.78 129.35,22.78 129.36,22.79 129.73,22.79 129.74,22.78 131.6,22.78 135.09,26.28 v1(139.98,26.28)
  BOTTOM w0.127: v1(139.98,26.28) 141.86,24.4
  BOTTOM w0.165: 141.86,24.4 142.05,24.21 144.02,24.21 144.73,23.49 J20.H29
GTX_CLKM: length 35.4
  BOTTOM w0.165: J20.D5 149.86,54.2 149.58,54.48 148.39,54.48 148.09,54.18 148.09,49.82 147.67,49.4 141.96,49.4 141.9,49.34 141.86,49.34
  BOTTOM w0.229: C32.2 123.38,42.66 124.14,42.66 126.11,44.63 127.35,44.63 128.39,43.59 130.1,43.59 131.12,44.6 135.67,44.6 140.41,49.34 141.86,49.34
GTX_CLKP: length 35.4
  BOTTOM w0.165: 141.86,49.72 141.9,49.72 141.96,49.66 147.56,49.66 147.83,49.93 147.83,54.29 148.28,54.74 149.56,54.74 149.86,55.04 J20.D4
  BOTTOM w0.229: C29.2 123.38,43.04 123.99,43.04 125.95,45.01 127.51,45.01 128.55,43.97 129.95,43.97 130.96,44.98 135.52,44.98 140.25,49.72 141.86,49.72
GTXCLKM: length 7.5
  BOTTOM w0.229: U2.2 117.15,44.81 117.21,44.75 117.21,44.27 118.8,42.67 121.46,42.67 R26.1 122.45,42.44 C32.1
GTXCLKP: length 7.5
  BOTTOM w0.229: C29.1 122.45,43.26 R27.1 121.49,43.05 118.96,43.05 118.63,43.39 118.63,43.67 118.73,43.78 118.73,44.06 118.53,44.26 118.24,44.26 118.14,44.16 117.86,44.16 117.59,44.43 117.59,44.75 117.65,44.81 U2.1
IFORCE: length 46.9
  L4_SIG w0.127: v1(8.55,46.22) 9.48,45.29 12.96,45.29 19.59,38.66 20.65,38.66 23.71,35.6 23.71,32.37 23.93,32.16 23.93,30.49 24.32,30.09 24.32,26.86 24.8,26.38 24.8,23.28 25.32,22.76 25.68,22.76 26.23,22.21 26.41,22.21 26.68,21.94 31.8,21.94 32.79,20.95 33.45,20.95 35.2,22.7 35.2,24.6 34.79,25 v1(34.79,25.01)
IOUTA: length 4.1
  TOP w0.483: R273.1 5.08,42.88 R269.1 J6.1
IOUTA_SE: length 4.1
  TOP w0.483: J7.1 R264.1 R274.1
IOUTAM: length 15
  TOP w0.483: U1.K12 27.49,29.72 R229.1 22.87,29.72 arc(22.34,29.82) 21.9,30.12 arc(21.37,31.04) 21.39,32.11 21.91,33.85 arc(21.97,34.16) 22,34.48 arc(21.7,35.21) L8.2 20.22,35.51 20.03,35.69 18.92,35.69 T7.6 18.89,35.71 R241.1
IOUTAP: length 15
  TOP w0.483: R248.1 T7.4 18.92,38.23 20.05,38.23 20.37,38.56 L7.1 20.98,38.56 arc(21.88,38.38) 22.65,37.87 arc(23.73,36.26) 24.1,34.35 24.1,32.99 arc(24.25,32.26) R239.1 25.57,30.73 R229.2 27.47,30.73 U1.L12
IOUTB: length 4.1
  TOP w0.483: R272.1 R266.1 J2.1
IOUTBM: length 15
  TOP w0.483: U1.D12 27.47,24.89 R199.1 25.7,24.89 R240.1 arc(24.36,23.34) 24.21,22.58 24.21,21.04 arc(23.85,19.25) 22.83,17.73 arc(22.05,17.2) L2.2 20.35,17.02 20.09,17.27 18.99,17.27 T5.6 R249.2
IOUTBP: length 15
  TOP w0.483: R238.2 18.95,19.83 T5.4 18.99,19.81 20.14,19.81 20.43,20.1 L1.1 arc(21.83,20.44) 22.03,21.21 21.47,23.95 arc(21.48,24.64) 21.77,25.27 arc(22.33,25.74) 23.04,25.91 R199.2 27.49,25.91 U1.E12
LMK LOCKED:
  vias: v1(131.09,22.28)
LMK_CLKIN: length 6.2
  BOTTOM w0.457: J4.1 94.11,62.84
  BOTTOM w0.483: R32.1 95.51,58.24 R33.1 94.68,59.07 arc(94.26,59.7) 94.11,60.45 94.11,62.84
LMK_CS: length 87.1
  TOP w0.127: v1(48.46,49.68) 49,50.22 49,51.82 50.57,53.39 53.21,53.39 55.09,55.27 55.09,59.18
  L4_SIG w0.127: v1(48.46,49.68) 48.46,49.78 47.18,51.07 47.18,52.16 47.4,52.37 53.64,52.37 58.37,47.65 66.14,47.65 66.85,46.94 84.56,46.94 85.89,48.27 86.47,48.27 86.73,48.53 86.73,49.21 88.07,50.55 88.65,50.55 90.07,51.97 91.9,51.97 93.54,50.33 95.57,50.33 95.76,50.52 103.05,50.52 103.24,50.33 104.49,50.33 104.62,50.2 104.98,50.2 105.11,50.33 105.93,50.33 106.88,49.38 106.88,47.62 v1(107.19,47.32)
  BOTTOM w0.127: U2.18 107.49,47.01 v1(107.19,47.32)
LMK_DACCLKSE: length 121.8
  TOP w0.381: C360.2 R287.1
  TOP w0.483: R287.1 113.97,53.57 114.48,53.06 114.48,45.03 113.84,44.4 113.84,39.93 115.24,38.53 v1(115.24,30.81)
  BOTTOM w0.406: v1(115.24,30.81) 115.24,27.36 103.66,15.77 41.94,15.77 41.61,16.1 34.57,16.1 34.06,16.61 28.6,16.61 27.51,17.7 v1(27.46,17.7)
LMK_SCK: length 87.8
  TOP w0.127: 55.09,62.61 53.9,61.42 53.9,55.63 52.93,54.66 49.78,54.66 49.25,54.13 v1(47.62,54.13)
  L4_SIG w0.127: v1(47.62,54.13) 47.98,53.77 54.92,53.77 56.34,52.35 56.67,52.35 60.3,48.72 66.45,48.72 67.41,47.75 74.78,47.75 75.16,48.13 83.85,48.13 88.67,52.96 91.92,52.96 94.53,55.56 99.56,55.56 100.19,54.93 100.98,54.93 102.31,53.59 105.69,53.59 106.98,52.3 106.98,51.49 107.62,50.85 108,50.85 108.94,49.91 108.94,48 v1(108.46,47.51)
  BOTTOM w0.127: U2.19 v1(108.46,47.51)
LMK_SDIO: length 85.2
  TOP w0.127: v1(47.62,52.98) 48.84,52.98 50.09,54.23 53.06,54.23 54.23,55.4 54.23,60.6 55.09,61.47
  L4_SIG w0.127: v1(107.72,47.7) 107.29,48.13 107.29,49.58 106.15,50.72 105.24,50.72 105.24,50.83 104.98,51.09 104.62,51.09 104.52,51 103.02,52.5 101.19,52.5 99.21,54.48 95.99,54.48 95.45,53.95 95.45,53.57 94.84,52.96 93.98,52.96 93.42,52.4 89.72,52.4 88.43,51.12 88.14,51.12 86.47,49.44 85.81,49.44 83.98,47.61 75.55,47.61 75.26,47.32 67.26,47.32 66.32,48.26 60.17,48.26 56.67,51.75 56.38,51.75 55.11,53.02 47.66,53.02 v1(47.62,52.98)
  BOTTOM w0.127: v1(107.72,47.7) 108.04,48.01 U2.20
LMK_SDO: length 98.9
  TOP w0.127: v1(47.62,51.84) 48.46,51.84 50.42,53.8 53.09,53.8 54.64,55.35 54.64,59.87 55.09,60.33
  L4_SIG w0.127: v1(116.31,42.04) 115.85,41.58 105.64,41.58 104.75,42.47 104.75,48.84 103.73,49.86 103.15,49.86 102.88,50.13 102.28,50.13 102.04,49.89 93.32,49.89 91.64,51.56 90.34,51.56 87.99,49.21 87.95,49.21 87.69,48.95 87.69,48.91 86.38,47.6 86.05,47.6 84.89,46.43 66.67,46.43 65.96,47.14 58.17,47.14 53.47,51.84 v1(47.62,51.84)
  BOTTOM w0.127: v1(116.31,42.04) 115.64,42.7 U2.5
NB7_RESET: length 140.3
  L3_PWR w0.127: v1(139.5,38.38) 137.1,40.78 129.17,40.78 128.94,41.01 118.63,41.01 117.82,41.82 116.83,41.82 116.41,41.4 106.43,41.4 105.92,41.91 105.16,41.91 100.87,46.2 v1(99.24,46.2)
  L4_SIG w0.127: v1(80.04,38.89) 78.21,40.72 78.21,42.06 76.61,43.66 68.68,43.66 65.79,46.56 57.99,46.56 57.4,47.14 53,47.14 52.13,46.28 47.96,46.28 45.77,48.46 v1(45.77,48.77)
  L6_PWR_SIG w0.127: v1(80.04,38.89) 80.04,38.79 82.17,36.65 93.65,36.65 94.23,36.07 98.35,36.07 99.92,37.64 99.92,42.88 99.24,43.56 v1(99.24,46.2)
  BOTTOM w0.127: U30.15 80.17,39.78 80.04,39.64 v1(80.04,38.89)
  BOTTOM w0.152: v1(45.77,48.77) 48.39,48.77 49,49.38 49,51.18 47.7,52.48 47.49,52.48 47.12,52.85 47.12,60.6 45.47,62.26 41.81,62.26 40.11,63.96 v1(40.08,63.96)
Net_409:
  vias: v3(142.24,50.16)
Net_410:
  vias: v3(142.24,51.44)
Net_411:
  vias: v3(142.24,9.52)
Net_413:
  vias: v3(142.24,13.33)
Net_415:
  vias: v3(142.24,17.14)
Net_417:
  vias: v3(142.24,20.95)
Net_419:
  vias: v3(142.24,24.77)
Net_421:
  vias: v3(142.24,28.58)
Net_423:
  vias: v3(142.24,32.38)
Net_424:
  vias: v3(142.24,34.93)
Net_425:
  vias: v3(142.24,36.2)
Net_426:
  vias: v3(142.24,38.73)
Net_427:
  vias: v3(142.24,40.01)
Net_428:
  vias: v3(142.24,42.55)
Net_431:
  vias: v3(142.24,47.62)
Net_432:
  vias: v3(142.24,59.05)
Net_433:
  vias: v3(143.51,48.9)
Net_434:
  vias: v3(143.51,51.44)
Net_435:
  vias: v3(143.51,52.7)
Net_436:
  vias: v3(143.51,10.79)
Net_438:
  vias: v3(143.51,14.61)
Net_440:
  vias: v3(143.51,18.41)
Net_442:
  vias: v3(143.51,22.23)
Net_445:
  vias: v3(143.51,28.58)
Net_448:
  vias: v3(143.51,33.66)
Net_449:
  vias: v3(143.51,36.2)
Net_450:
  vias: v3(143.51,37.47)
Net_451:
  vias: v3(143.51,40.01)
Net_452:
  vias: v3(143.51,41.27)
Net_454:
  vias: v3(143.51,45.09)
Net_455:
  vias: v3(143.51,47.62)
Net_456:
  vias: v3(144.78,50.16)
Net_458:
  vias: v3(144.78,53.98)
Net_459:
  vias: v3(144.78,9.52)
Net_460:
  vias: v3(144.78,55.25)
Net_461:
  vias: v3(144.78,12.06)
Net_463:
  vias: v3(144.78,15.88)
Net_465:
  vias: v3(144.78,19.69)
Net_468:
  vias: v3(144.78,28.58)
Net_472:
  vias: v3(144.78,57.79)
Net_473:
  vias: v3(144.78,42.55)
Net_476:
  vias: v3(144.78,47.62)
Net_477:
  vias: v3(144.78,59.05)
Net_478:
  vias: v3(146.05,10.79)
Net_484:
  vias: v3(146.05,22.23)
Net_485:
  vias: v3(146.05,56.52)
Net_488:
  vias: v3(146.05,28.58)
Net_492:
  vias: v3(146.05,57.79)
Net_493:
  vias: v3(146.05,36.2)
Net_494:
  vias: v3(146.05,37.47)
Net_496:
  vias: v3(146.05,45.09)
Net_497:
  vias: v3(147.32,50.16)
Net_498:
  vias: v3(147.32,51.44)
Net_500:
  vias: v3(147.32,9.52)
Net_501:
  vias: v3(147.32,55.25)
Net_502:
  vias: v3(147.32,12.06)
Net_504:
  vias: v3(147.32,15.88)
Net_506:
  vias: v3(147.32,19.69)
Net_511:
  vias: v3(147.32,28.58)
Net_514:
  vias: v3(147.32,38.73)
Net_515:
  vias: v3(147.32,40.01)
Net_516:
  vias: v3(147.32,42.55)
Net_518:
  vias: v3(147.32,59.05)
Net_522:
  vias: v3(148.59,10.79)
Net_528:
  vias: v3(148.59,22.23)
Net_529:
  vias: v3(148.59,56.52)
Net_532:
  vias: v3(148.59,28.58)
Net_536:
  vias: v3(148.59,57.79)
Net_537:
  vias: v3(148.59,36.2)
Net_538:
  vias: v3(148.59,37.47)
Net_539:
  vias: v3(148.59,40.01)
Net_540:
  vias: v3(148.59,41.27)
Net_544:
  vias: v3(149.86,48.9)
Net_545:
  vias: v3(149.86,50.16)
Net_546:
  vias: v3(149.86,9.52)
Net_547:
  vias: v3(149.86,12.06)
Net_549:
  vias: v3(149.86,15.88)
Net_553:
  vias: v3(149.86,20.95)
Net_554:
  vias: v3(149.86,22.23)
Net_558:
  vias: v3(149.86,29.84)
Net_559:
  vias: v3(149.86,31.12)
Net_561:
  vias: v3(149.86,34.93)
Net_562:
  vias: v3(149.86,45.09)
Net_563:
  vias: v3(149.86,46.36)
Net_564:
  vias: v3(149.86,59.05)
Net_565:
  vias: v3(151.13,51.44)
Net_566:
  vias: v3(151.13,52.7)
Net_567:
  vias: v3(151.13,10.79)
Net_569:
  vias: v3(151.13,15.88)
Net_571:
  vias: v3(151.13,20.95)
Net_572:
  vias: v3(151.13,22.23)
Net_575:
  vias: v3(151.13,31.12)
Net_576:
  vias: v3(151.13,32.38)
Net_577:
  vias: v3(151.13,36.2)
Net_578:
  vias: v3(151.13,46.36)
Net_579:
  vias: v3(151.13,47.62)
Net_580:
  vias: v3(152.4,48.9)
Net_581:
  vias: v3(152.4,50.16)
Net_582:
  vias: v3(152.4,53.98)
Net_583:
  vias: v3(152.4,9.52)
Net_584:
  vias: v3(152.4,55.25)
Net_587:
  vias: v3(152.4,28.58)
Net_588:
  vias: v3(152.4,29.84)
Net_590:
  vias: v3(152.4,34.93)
Net_591:
  vias: v3(152.4,38.73)
Net_592:
  vias: v3(152.4,40.01)
Net_593:
  vias: v3(152.4,43.82)
Net_594:
  vias: v3(152.4,45.09)
Net_595:
  vias: v3(152.4,59.05)
Net_596:
  vias: v3(153.67,51.44)
Net_597:
  vias: v3(153.67,52.7)
Net_598:
  vias: v3(153.67,56.52)
Net_599:
  vias: v3(153.67,57.79)
Net_600:
  vias: v3(153.67,36.2)
Net_601:
  vias: v3(153.67,37.47)
Net_602:
  vias: v3(153.67,41.27)
Net_603:
  vias: v3(153.67,42.55)
Net_604:
  vias: v3(153.67,46.36)
Net_605:
  vias: v3(153.67,47.62)
OSCI: length 13.5
  BOTTOM w0.229: U4.2 31.8,51.59 31.74,51.65 28.54,51.65 27.25,50.36 27.25,49.43 27.86,48.82 27.86,46.91 27.3,46.36 26.49,46.36 C78.1 25.92,46.37 Y2.1
OSCINN: length 5.8
  BOTTOM w0.229: C51.2 117.14,57.56 116.87,57.56 116.74,57.43 116.74,57.23 116.59,57.07 116.41,57.07 116.28,57.2 116.28,57.42 116.15,57.55 115.97,57.55 115.59,57.16 115.59,55.78 115.64,55.72 U2.44
  BOTTOM w0.381: C50.2 118.11,57.35 C51.2
OSCINP: length 5.8
  BOTTOM w0.229: U2.43 115.14,55.72 115.2,55.78 115.2,57.32 115.82,57.94 117.12,57.94 117.35,58.17
  BOTTOM w0.381: C45.2 118.11,58.17 117.35,58.17
OSCN: length 2.4
  BOTTOM w0.381: C49.2 120.42,57.38 R49.2 R54.1 118.87,57.35 C50.1
OSCO: length 13.5
  BOTTOM w0.229: U4.3 31.8,52.09 31.74,52.03 28.38,52.03 26.77,50.42 26.39,50.42 24.52,52.29 24.07,52.29 23.77,51.99 23.77,51.25 C79.1 23.85,50.84 24.78,49.91
OSCP: length 2.4
  BOTTOM w0.381: C44.2 120.42,58.14 120.4,58.17 118.87,58.17 C45.1
PLL2 LOCKED:
  vias: v1(131.12,30.21)
RX0N: length 13.8
  TOP w0.229: U1.M4 33.81,31.59 33.81,32.74 34.02,32.95 arc(34.22,33.04) 34.43,32.95 arc(34.63,32.87) 34.83,32.95 34.91,33.03 arc(35,33.23) 34.91,33.44 arc(34.83,33.64) 34.91,33.84 36.4,35.33 44.27,35.33 44.42,35.18
RX0P: length 13.8
  TOP w0.229: 44.42,35.94 44.2,35.71 36.24,35.71 33.43,32.9 33.43,31.65 U1.M5
RX1N: length 10.7
  TOP w0.229: 44.42,33.4 44.27,33.25 36.19,33.25 34.97,32.02 34.97,31.59 U1.M3
RX1P: length 10.7
  TOP w0.229: U1.M2 35.4,31.6 35.4,31.92 36.35,32.87 36.76,32.87 arc(36.94,32.79) 37.01,32.61 arc(37.09,32.43) 37.27,32.36 37.45,32.36 arc(37.62,32.43) 37.7,32.61 arc(37.77,32.79) 37.95,32.87 44.2,32.87 44.42,32.64
RX2N: length 8.5
  TOP w0.229: 44.42,29.97 44.22,30.18 43.3,30.18 42.63,30.85 36.62,30.85 U1.L1
RX2P: length 8.5
  TOP w0.229: U1.M1 36.58,31.23 42.79,31.23 43.46,30.56 44.25,30.56 44.42,30.73
RX3N: length 8.9
  TOP w0.229: 44.42,28.07 44.25,27.89 43.76,27.89 42.01,29.64 36.56,29.64 U1.K1
RX3P: length 8.9
  TOP w0.229: U1.J1 36.64,29.26 41.85,29.26 43.61,27.51 44.22,27.51 44.42,27.3
RX4N: length 9.8
  TOP w0.229: U1.F1 36.61,26.39 39.85,26.39 43.71,22.53 44.22,22.53 44.42,22.73
RX4P: length 9.8
  TOP w0.229: U1.E1 36.58,26.01 39.7,26.01 43.56,22.15 44.25,22.15 44.42,21.97
RX5N: length 10.7
  TOP w0.229: U1.B1 36.66,23.14 37.59,23.14 43.51,17.22 44.25,17.22 44.42,17.4
RX5P: length 10.6
  TOP w0.229: 44.42,16.64 44.22,16.84 43.35,16.84 37.43,22.76 36.53,22.76 U1.A1
RX6N: length 10.2
  TOP w0.229: 44.42,19.3 44.25,19.48 43.48,19.48 38.55,24.41 36.62,24.41 36.42,24.22 36.39,24.22 U1.C1
RX6P: length 10.3
  TOP w0.229: U1.D1 36.61,24.79 38.71,24.79 43.64,19.86 44.22,19.86 44.42,20.07
RX7N: length 9.4
  TOP w0.229: 44.42,24.64 44.25,24.81 43.69,24.81 40.86,27.64 36.61,27.64 U1.G1
RX7P: length 9.4
  TOP w0.229: U1.H1 36.59,28.02 41.02,28.02 43.85,25.19 44.21,25.19 44.42,25.4
SCLK: length 18.4
  TOP w0.102: 29.57,31.73 29.57,31.28 29.99,30.86 v1(29.99,30.61)
  TOP w0.127: 29.57,31.73 29.57,35.05 28.07,36.55 27.84,36.55 26.14,38.25 25.88,38.25 21.64,42.49 20.83,42.49 20.52,42.8 20.52,44.2 v1(20.61,44.28)
SDENB: length 25.7
  TOP w0.102: 30.47,31.73 U1.M8
  TOP w0.127: v1(18.6,44.28) 18.6,45.88 18.92,46.2 23.19,46.2 23.67,45.72 23.67,42.29 27.77,38.19 27.77,37.49 28.02,37.25 28.61,37.25 30.38,35.48 30.38,31.82 30.47,31.73
  BOTTOM w0.127: R290.1 18.59,44.29 v1(18.6,44.28)
SDIO: length 23.3
  TOP w0.102: U1.M10 29.19,31.73
  TOP w0.127: 29.19,31.73 29.19,34.72 26.68,37.22 25.96,37.22 25.72,37.47 25.72,37.93 21.62,42.04 17.27,42.04 16.61,42.7 16.61,44.26 v1(16.59,44.28)
  BOTTOM w0.127: R291.1 16.56,44.31 v1(16.59,44.28)
SDO: length 17.5
  TOP w0.102: 29.99,31.73 U1.M9
  TOP w0.127: 29.99,31.73 29.99,35.16 28.24,36.91 27.86,36.91 27.38,37.39 27.38,37.64 26.2,38.82 25.84,38.82 25.53,39.13 25.53,39.5 22.62,42.41 v1(22.62,44.28)
  BOTTOM w0.127: R288.1 22.66,44.25 v1(22.62,44.28)
SLEEP: length 82.6
  L4_SIG w0.127: v1(37.03,37.06) 37.47,37.06 37.66,36.87 37.66,36.85 39.31,35.2 39.31,33.96 40.4,32.87 41.66,32.87 41.75,32.78 48.37,32.78 48.44,32.71 60.65,32.71 61.52,33.58 62.97,33.58 63.65,34.26 79.2,34.26 80.02,35.09 99.4,35.09 100.23,35.92 100.23,37.08 102.21,39.07 JP1.2
  BOTTOM w0.102: 30.66,31.73 30.66,31.53 30.79,31.4 v1(30.79,30.61)
  BOTTOM w0.127: v1(37.03,37.06) 37.03,36.7 34.16,33.83 31.14,33.83 30.66,33.35 30.66,31.73
SPARE1: length 81.9
  L4_SIG w0.127: J11.3 98.98,38.56 98.98,36.65 97.92,35.59 72.44,35.59 71.74,36.28 70.91,36.28 70.21,35.59 61.88,35.59 60.01,33.72 56.71,33.72 56.44,33.99 50.08,33.99 50.07,34 49.7,34 49.69,33.99 49.07,33.99 48.26,33.17 40.9,33.17 40.25,33.83 40.25,35.26 38.47,37.03 v1(38.1,37.03)
  BOTTOM w0.102: 31.04,31.73 31.04,31.7 31.59,31.15 v1(31.59,30.61)
  BOTTOM w0.127: v1(38.1,37.03) 38.07,37.03 33.93,32.89 31.27,32.89 31.01,32.64 31.01,31.76 31.04,31.73 ; R10.2 97.82,39.78 J11.3
SPARE2: length 74.7
  L4_SIG w0.127: v1(40.26,37.03) 40.63,37.03 41.51,36.16 42.22,36.16 42.62,36.56 42.62,37.54 43.19,38.11 56.02,38.11 57.18,36.96 70.29,36.96 70.53,37.2 72.12,37.2 72.36,36.96 81.87,36.96 81.88,36.94 82.64,36.94 86.47,40.78 87.26,40.78 87.52,41.04 87.52,42.61 88.37,43.46 96.42,43.46 J11.7
  BOTTOM w0.102: v1(32.39,30.61) 32.84,31.06 34.06,31.06 34.73,31.73 34.75,31.73
  BOTTOM w0.127: v1(40.26,37.03) 38.66,35.43 38.45,35.43 34.75,31.73
SPARE3: length 74.5
  L4_SIG w0.127: J11.1 96.65,36.07 72.39,36.07 71.87,36.59 70.78,36.59 70.26,36.07 61.57,36.07 61.12,35.62 59.7,35.62 58.72,34.65 57.05,34.65 56.72,34.97 52.42,34.97 52.07,34.62 48.13,34.62 47.47,35.28 40.89,35.28 v1(39.14,37.03)
  BOTTOM w0.102: v1(31.59,29.81) 31.59,29.81 32.01,30.24 32.01,31.16 31.94,31.23 31.94,31.6 32.08,31.73
  BOTTOM w0.127: 32.08,31.73 32.2,31.86 33.51,31.86 37.38,35.73 37.83,35.73 v1(39.14,37.03) ; J11.1 97.82,37.19 R9.2
SPARE4: length 76.6
  TOP w0.102: 32.09,31.73 31.77,31.41 U1.M7
  TOP w0.127: v1(35.86,37.06) 32.92,37.06 32.2,36.34 32.2,33.97 32.59,33.58 32.59,32.23 32.09,31.73
  L4_SIG w0.127: v1(35.86,37.06) 36.96,38.15 38.73,38.15 39.68,37.2 39.68,36.98 40.95,35.71 48.39,35.71 49.02,35.08 51.89,35.08 52.83,36.02 54.38,36.02 54.94,36.58 70.34,36.58 70.65,36.89 71.99,36.89 72.31,36.58 82.93,36.58 86.44,40.08 87.2,40.08 88.16,41.05 96.55,41.05 J11.5
STAT 0:
  vias: v1(131.12,27.56)
STAT 1:
  vias: v1(131.12,24.95)
SYNC: length 6
  TOP w0.483: v1(115.14,43.1) 115.37,42.88 118.14,42.88 R148.2
  BOTTOM w0.305: U2.6 v1(115.14,43.1)
SYNC0BN: length 125
  TOP w0.229: v1(147.32,46.36) 146.95,46.72 140.2,46.72 139.74,46.26 arc(139.65,46.06) 139.74,45.86 arc(139.82,45.65) 139.74,45.45 139.66,45.37 arc(139.45,45.29) 139.25,45.37 arc(139.05,45.46) 138.84,45.37 133.74,40.27 132.15,40.27 126.85,34.98 123.19,34.98 113.03,24.82 61.72,24.82 59.61,26.92 58.42,26.92 v1(58.14,26.64)
  BOTTOM w0.102: 36.79,24.93 36.74,24.93 36.51,24.69 35.96,24.15 35.96,24.06 35.74,23.84 35.43,23.84 35.06,24.21 v1(34.79,24.21)
  BOTTOM w0.229: v1(58.14,26.64) 57.86,26.92 38.86,26.92 36.94,25.01 36.91,25.01 36.83,24.93 36.79,24.93
SYNC0BP: length 125
  TOP w0.229: v1(58.14,27.59) 58.42,27.3 59.77,27.3 61.87,25.2 112.87,25.2 123.03,35.36 126.7,35.36 131.99,40.65 133.58,40.65 140.04,47.1 146.8,47.1 v1(147.32,47.62)
  BOTTOM w0.102: v1(33.99,24.21) 34.22,24.21 34.6,24.59 36.04,24.59 36.68,25.22 36.68,25.28 36.79,25.39
  BOTTOM w0.229: v1(58.14,27.59) 57.86,27.3 38.7,27.3 36.79,25.39
SYNC1BN: length 130.8
  L4_SIG w0.127: v1(147.32,34.93) 147.32,35.29 147.45,35.42 148.8,35.42 149.03,35.18 149.03,34.29 147.14,32.4 143.16,32.4 134.52,23.76 127.71,23.76 126.96,23.01 103.53,23.01 103.27,23.27 102.74,23.86 v1(102.76,24.16)
  BOTTOM w0.102: v1(32.39,24.21) 32.39,24.2 31.98,23.79 31.98,23.19 31.83,23.04 31.83,22.45 31.78,22.4
  BOTTOM w0.229: 31.78,22.4 31.78,21.9 32.8,20.88 34.05,20.88 36.4,23.22 37.27,23.22 39.09,25.04 101.72,25.04 102.6,24.16 v1(102.76,24.16)
SYNC1BP: length 132.4
  L4_SIG w0.127: v1(147.32,36.2) 147.32,35.83 147.45,35.7 148.91,35.7 149.31,35.3 149.31,34.17 147.26,32.12 143.28,32.12 134.64,23.48 127.83,23.48 127.08,22.73 103.41,22.73 103.06,23.08 102.5,23.71 102.26,23.72 v1(102.23,23.69)
  BOTTOM w0.102: 31.39,22.4 31.43,22.43 31.43,22.92 31.21,23.14 31.21,23.67 31.6,24.06 31.6,24.2 v1(31.59,24.21) ; 35.99,22.28 36.01,22.3
  BOTTOM w0.229: 35.99,22.28 34.21,20.5 32.64,20.5 31.39,21.75 31.39,22.4 ; 36.01,22.3 36.55,22.84 37.43,22.84 39.24,24.66 101.56,24.66 102.2,24.02 102.2,23.72 v1(102.23,23.69)
SYSREF+: length 3.5
  BOTTOM w0.229: R40.1 111.4,43.21 R41.1 111.61,43.46 111.61,43.89 111.21,44.28 111.21,44.74 111.14,44.81 U2.14
SYSREF-: length 3.5
  BOTTOM w0.229: U2.13 111.64,44.81 111.59,44.76 111.59,44.44 111.99,44.04 111.99,43.43 R42.1 112.17,43.21 R39.1
SYSREF-N: length 7.7
  TOP w0.229: v1(37.78,17.67) 37.55,17.89 36.89,17.89 34.19,20.59 34.19,22.41 U1.A4
  BOTTOM w0.229: v1(37.78,17.67) 37.81,17.7 R104.2
SYSREF-P: length 7.7
  TOP w0.229: v1(37.78,18.5) 37.55,18.27 37.05,18.27 35.7,19.62 arc(35.63,19.8) 35.7,19.99 arc(35.78,20.17) 35.7,20.35 35.59,20.47 arc(35.4,20.55) 35.22,20.47 arc(35.03,20.39) 34.85,20.47 34.57,20.75 34.57,22.39 U1.A3
  BOTTOM w0.229: R103.2 37.79,18.48 v1(37.78,18.5)
SYSREFN: length 115
  BOTTOM w0.229: R104.1 39.71,17.7 39.94,17.93 46.03,17.93 46.63,18.53 46.63,19.41 47.01,19.79 47.55,19.79 47.93,19.41 47.93,18.53 48.53,17.93 49.38,17.93 49.98,18.53 49.98,19.41 50.36,19.79 50.9,19.79 51.28,19.41 51.28,18.53 51.88,17.93 52.73,17.93 53.34,18.53 53.34,19.41 53.72,19.79 54.25,19.79 54.63,19.41 54.63,18.53 55.23,17.93 56.09,17.93 56.69,18.53 56.69,19.41 57.07,19.79 57.6,19.79 57.98,19.41 57.98,18.53 58.59,17.93 59.44,17.93 60.04,18.53 60.04,19.41 60.42,19.79 60.96,19.79 61.34,19.41 61.34,18.53 61.94,17.93 62.79,17.93 63.39,18.53 63.39,19.41 63.77,19.79 64.31,19.79 64.69,19.41 64.69,18.53 65.29,17.93 66.14,17.93 66.75,18.53 66.75,19.41 67.13,19.79 67.66,19.79 68.04,19.41 68.04,18.53 68.65,17.93 69.5,17.93 70.1,18.53 70.1,19.41 70.48,19.79 71.02,19.79 71.4,19.41 71.4,18.53 72,17.93 72.85,17.93 73.45,18.53 73.45,19.41 73.88,19.84 74.42,19.84 74.75,19.51 74.75,18.53 75.35,17.93 102.22,17.93 111.15,26.87 111.15,33.15 112.29,34.29 112.29,35.84 111.2,36.93 111.2,38.35 111.98,39.12 111.98,40.73 R107.1 112.19,41.71 R39.2
SYSREFP: length 115
  BOTTOM w0.229: R103.1 39.71,18.48 39.88,18.31 45.87,18.31 46.25,18.69 46.25,19.57 46.85,20.17 47.7,20.17 48.31,19.57 48.31,18.69 48.69,18.31 49.22,18.31 49.6,18.69 49.6,19.57 50.2,20.17 51.06,20.17 51.66,19.57 51.66,18.69 52.04,18.31 52.58,18.31 52.95,18.69 52.95,19.57 53.56,20.17 54.41,20.17 55.01,19.57 55.01,18.69 55.39,18.31 55.93,18.31 56.31,18.69 56.31,19.57 56.91,20.17 57.76,20.17 58.37,19.57 58.37,18.69 58.74,18.31 59.28,18.31 59.66,18.69 59.66,19.57 60.26,20.17 61.12,20.17 61.72,19.57 61.72,18.69 62.1,18.31 62.63,18.31 63.01,18.69 63.01,19.57 63.62,20.17 64.47,20.17 65.07,19.57 65.07,18.69 65.45,18.31 65.99,18.31 66.37,18.69 66.37,19.57 66.97,20.17 67.82,20.17 68.42,19.57 68.42,18.69 68.8,18.31 69.34,18.31 69.72,18.69 69.72,19.57 70.32,20.17 71.17,20.17 71.78,19.57 71.78,18.69 72.16,18.31 72.69,18.31 73.07,18.69 73.07,19.57 73.73,20.22 74.57,20.22 75.13,19.66 75.13,18.69 75.51,18.31 102.06,18.31 102.83,19.08 arc(102.91,19.28) 102.83,19.48 arc(102.75,19.68) 102.83,19.87 102.92,19.96 arc(103.12,20.05) 103.31,19.96 arc(103.51,19.88) 103.71,19.96 110.77,27.03 110.77,33.3 111.91,34.45 111.91,35.68 110.82,36.77 110.82,38.51 111.59,39.28 111.59,40.73 R106.1 111.38,41.71 R40.2
